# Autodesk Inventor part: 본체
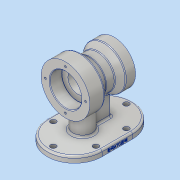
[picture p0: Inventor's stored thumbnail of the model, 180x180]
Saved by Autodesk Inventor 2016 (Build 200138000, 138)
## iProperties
Created: 2020-01
Part Number: 본체
Material: 알루미늄 6061
Document SubType Name: Modeling
Designer: woori
Density: 2.7 g/cm^3
Appearance: 알루미늄 - 평지
Mass: 938.055 g
Surface Area: 654.99 cm^2
Volume: 347.428 cm^3
Author: woori
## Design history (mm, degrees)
sketch "스케치1"
  geometry: L1 (0, 0)-(0, 40); L2 (0, 40)-(24, 40); L3 (24, 40)-(38.897, 27.5); L4 (38.897, 27.5)-(53.289, 27.5); L5 (53.289, 27.5)-(64, 35); L6 (64, 35)-(80, 35); L7 (80, 35)-(80, 0); L8 (0, 0)-(80, 0); L9 (32.583, 27.5)-(57.394, 27.5)
  constraints: 18 end point, 2 horizontal, 2 parallel, 2 perpendicular, 1 horizontal alignment, 1 vertical
  dimensions: "d1" = 24 distance of L1.end L2.end; "d2" = 16 distance of L5.end L6.end; "d3" = 80 distance between parallel lines of L1 L7; "d4" = 80 diameter of L2 L8; "d5" = 55 diameter of L4 L8; "d6" = 70 diameter of L6 L8; "d72" = 40 deg angle of L9 L3; "d73" = 35 deg angle of L5 L9
revolve "회전1" sketch "스케치1" stored, may be unused: angle "d7" = 90 deg
node "작업 평면1"
sketch "스케치2"
  geometry: L1 (40, 0)-(-40, 0) reference; L2 (-45, 15)-(-45, 65); L3 (45, 15)-(45, 65); L4 (45, 15)-(95, 15); A1 r 45 centre (0, 15) between (-45, 15) and (45, 15); A2 r 45 centre (0, 65) between (45, 65) and (-45, 65); 1 further point
  constraints: 6 end point, 4 point on circle, 2 centre point, 2 vertical, 1 horizontal, 1 perpendicular, 1 tangent
  dimensions: "d10" = 90 diameter of A1; "d13" = 30 distance edge to line of A1 L1; "d14" = 50 distance of L2.end L2.start; "d15" = 50 distance of L3.end L3.start; "d16" = 90 deg angle of L4 L3 (derived)
extrude "돌출1" join sketch "스케치2" distance "d17" = 10; taper "d18" = 0 deg
sketch "스케치3"
  geometry: L1 (35, 80)-(-35, 80) reference; L2 (-5, 70)-(5, 70); L3 (5, 70)-(5, 43.199); L4 (-5, 43.199)-(-5, 70); L5 (0, -30)-(26.772, -30); A1 r 16 centre (0, 28) between (-5, 43.199) and (5, 43.199); A2 r 45 centre (0, 15) between (-45, 15) and (45, 15) reference; 2 further points
  constraints: 8 end point, 3 point on circle, 2 horizontal, 1 centre point, 1 parallel, 1 perpendicular, 1 tangent, 1 vertical alignment
  dimensions: "d19" = 10 distance between parallel lines of L1 L2; "d20" = 10 distance of L2.start L2.end; "d22" = 32 diameter of A1; "d23" = 58 distance from line of A1.centre L5
extrude "돌출2" join sketch "스케치3" distance "d24" = 70; taper "d25" = 0 deg
sketch "스케치5" dims "d36" = 66
  geometry: 3 further points
  constraints: 1 coincident, 1 vertical alignment, 2 other
hole "구멍1" sketch "스케치5" at (0, 33) diameter "d37" = 3.242; stored, may be unused: countersink angle "d41" = 90 deg, drill point angle "d43" = 118 deg; dims "d38" = 9, "d39" = 4, "d40" = 2, "d42" = 11
sketch "스케치6" dims "d47" = 55
  geometry: 3 further points
  constraints: 1 coincident, 1 vertical alignment, 2 other
hole "구멍2" sketch "스케치6" at (0, -27.5) diameter "d48" = 3.242; stored, may be unused: countersink angle "d52" = 90 deg, drill point angle "d54" = 118 deg; dims "d49" = 9, "d50" = 4, "d51" = 2, "d53" = 11
sketch "스케치8"
  geometry: L1 (0, -45)-(-10, -45) reference; L2 (0, 95)-(0, 50) reference; 2 further points
  constraints: 1 other
  dimensions: "d68" = 4 distance from line of L2 point (-4, 25); "d69" = 70 distance from line of L1 point (-4, 25)
feature "엠보싱1" sketch "스케치8" dims "d70" = 0.5, "d71" = 0
fillet "모깎기1" dims "d74" = 3
sketch "스케치9"
  geometry: L1 (0, -40)-(0, 40) reference; L2 (0, 26)-(20, 26); L3 (-9.282, 0)-(95.754, 0); L4 (80, -35)-(80, 35) reference; L5 (64, -34.641)-(64, 35) reference; L6 (80, 20)-(63, 20); L7 (20, 16)-(63, 16); L8 (20, 26)-(20, 16); L9 (63, 20)-(63, 16); L10 (80, 20)-(80, 0); L11 (0, 26)-(0, 0); L12 (0, -1.621)-(0, 1.621) reference; L13 (0, 0)-(80, 0); 2 further points
  constraints: 18 end point, 4 horizontal, 3 midpoint, 2 collinear, 2 point on line, 1 horizontal alignment, 1 parallel, 1 vertical
  dimensions: "d75" = 20 distance of L2.start L2.end; "d76" = 52 diameter of L2 L3; "d78" = 17 distance of L6.start L6.end; "d79" = 40 diameter of L6 L3; "d80" = 32 diameter of L7 L3
revolve "회전3" sketch "스케치9" stored, may be unused: angle "d81" = 90 deg
chamfer "모따기1" distance "d82" = 1; stored, may be unused: second distance "d83" = 2, angle "d84" = 45 deg
fillet "모깎기2" dims "d85" = 0.3
fillet "모깎기3" dims "d86" = 3
fillet "모깎기4" dims "d87" = 3
sketch "스케치10"
  geometry: L1 (-45, 65)-(-45, 15) reference; L2 (45, 15)-(45, 65) reference; L3 (-35, 15)-(-35, 65); L4 (35, 65)-(35, 15); A1 r 45 centre (0, 15) between (-45, 15) and (45, 15) reference; A2 r 45 centre (0, 65) between (45, 65) and (-45, 65) reference; A3 r 35 centre (0, 15) between (-35, 15) and (35, 15); A4 r 35 centre (0, 65) between (35, 65) and (-35, 65); 7 further points
  constraints: 6 point on circle, 4 end point, 3 coincident, 2 centre point, 1 point on line, 3 other
  dimensions: "d90" = 10 radial gap between concentric circles of A1 A3
hole "구멍4" sketch "스케치10" at (0, -20), (0, 100), (35, 15), (35, 65), (-35, 15), (-35, 65) diameter "d91" = 9; stored, may be unused: countersink angle "d95" = 90 deg, drill point angle "d97" = 0 deg; dims "d92" = 9, "d93" = 4, "d94" = 2, "d96" = 11
fillet "모깎기6" dims "d98" = 3
node "솔리드1"
pattern_circular "원형 패턴1" dims angle "d45" = 360 deg
pattern_circular "원형 패턴2" dims angle "d56" = 360 deg
